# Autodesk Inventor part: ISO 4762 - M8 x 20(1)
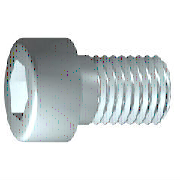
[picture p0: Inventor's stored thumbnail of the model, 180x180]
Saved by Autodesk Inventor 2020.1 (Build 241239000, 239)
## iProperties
Created: 2019-01
Part Number: ISO 4762 - M8 x 20(1)
Material: Edelstahl, 440C
Description: Innensechskantschraube
Document SubType Name: Modeling
Standard: ISO 4762
Designer: lutzd
Standard Revision: Fourth edition 2004-03-01
Standards Organization: ISO
Language: de-DE
Size Designation: M8 x 20
Categories: <MemberInstance><Categories><Category DisplayName="Verbindungselemente" InternalName="e4da775c-781d-43d5-af7c-5136215cf5a6" Mnemonic="FSTN"><Category DisplayNam
Mass: 14.7692 g
Surface Area: 11.5903 cm^2
Volume: 1.9057 cm^3
Density: 7.75 g/cm^3
Appearance: Halbpoliert
IsCustomPart: 0
Author: lutzd
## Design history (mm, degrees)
workplane "Work Plane1"
fillet "Fillet2" dims "d30" = 0.1 (= R)
sketch "Skizze1"
  geometry: L1 (-2, 0)-(20, 0); L2 (20, 0)-(20, 4); L3 (20, 4)-(3.125, 4); L4 (3.125, 4)-(2.358, 4); L5 (2.358, 4)-(0, 4); L6 (0, 4)-(0, 6.5); L7 (0, 6.5)-(-8, 6.5); L8 (-8, 6.5)-(-8, 3.464); L9 (-8, 3.464)-(-4, 3.464); L10 (-4, 3.464)-(-2, 0); L11 (-13.6, 0)-(25.6, 0) reference; L12 (0, -1.3)-(0, 7.8) reference; L13 (3.125, 4)-(0, 4)
  constraints: 22 end point, 6 parallel, 2 collinear, 2 perpendicular, 1 horizontal, 1 point on line
  dimensions: "d1" = 16.875 distance from line of L3.end L2 (= GEL); "d2" = 0.76691 distance of L4.end L3.end (computed from GAL); "d3" = 8 distance between parallel lines of L8 L6 (= KOH); "d4" = 4 distance of L8.end L9.end (= INTI); "d5" = 60 deg angle of L10 L1; "d6" = 8 diameter of L3 L1 (= GD); "d7" = 8 diameter of L5 L1 (= BDM); "d8" = 6.9282 diameter of L9 L1 (= 1.1547 x SW); "d9" = 13 diameter of L7 L1 (= KOD); "d26" = 20 distance between parallel lines of L12 L2 (= NLG)
revolve "Körper" sketch "Skizze1" stored, may be unused: angle "d10" = 90 deg
sketch "Skizze2"
  geometry: L1 (0, -9.1)-(0, 9.1) reference; L2 (-9.1, 0)-(9.1, 0) reference; L3 (3.464, 0)-(1.732, -3); L4 (1.732, -3)-(-1.732, -3); L5 (-1.732, -3)-(-3.464, 0); L6 (-3.464, 0)-(-1.732, 3); L7 (-1.732, 3)-(1.732, 3); L8 (1.732, 3)-(3.464, 0); 2 further points
  constraints: 12 end point, 1 coincident, 1 horizontal alignment, 1 point on line, 12 other
extrude "Loch" join sketch "Skizze2" stored distance "d11" = 10; taper "d12" = 0 deg
body "Solid1"
fillet "Rundung1" dims "d17" = 0.8 (= RR)
feature "Gewinde" dims "d13" = 16.875 (= GEL), "d14" = 0
chamfer "Fase1" distance "d15" = 0.76681 (= -0.5 x SPD + 0.5 x GD); stored, may be unused: second distance "d16" = 0.76681 (= GUL), angle "d27" = 45 deg
other parameters: "GD" = 8 [user parameter; used in 2 equation terms], "NLG" = 20 [user parameter; used in 1 equation term], "GEL" = 16.875 [user parameter; used in 2 equation terms], "KOD" = 13 [user parameter; used in 1 equation term], "KOH" = 8 [user parameter; used in 1 equation term], "INTI" = 4 [user parameter; used in 1 equation term], "GAL" = 0.76681 (= 0.61345 x PTC) [user parameter; used in 1 equation term], "GUL" = 0.76681 (= 0.61345 x PTC) [user parameter; used in 1 equation term], "BDM" = 8 (= NND) [user parameter; used in 1 equation term], "SW" = 6 [user parameter; used in 2 equation terms], "RR" = 0.8 [user parameter; used in 1 equation term], "SPD" = 6.46637 (= NND - 1.2269 x PTC) [user parameter; used in 1 equation term], "d19" = 0, "d28" = 0, "d29" = 0, "R" = 0.1 [user parameter; used in 1 equation term], "TOA" = 30 deg [user parameter], "GD1" = 6.46637 (= THREADDIA - 1.2269 x PTC) [user parameter], "THREADDIA" = 8 [user parameter; used in 1 equation term], "FAWI" = 45 deg [user parameter], "TPU" = 8 (computed from PTC) [user parameter], "PTC" = 1.25 [user parameter; used in 5 equation terms], "NND" = 8 [user parameter; used in 2 equation terms], "E0" = 6.93 (= 1.155 x SW) [user parameter]
